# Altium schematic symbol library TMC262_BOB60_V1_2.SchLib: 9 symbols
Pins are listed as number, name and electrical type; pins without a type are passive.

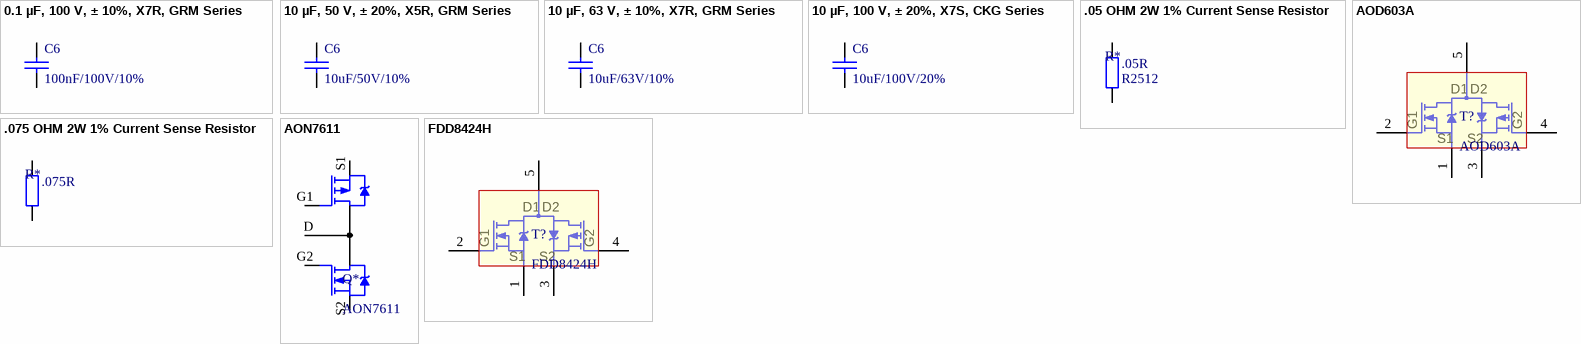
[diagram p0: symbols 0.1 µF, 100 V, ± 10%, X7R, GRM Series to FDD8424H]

## 0.1 µF, 100 V, ± 10%, X7R, GRM Series
designator C6, comment 100nF/100V/10%
SMD Multilayer Ceramic Capacitor, 0603 [1608 Metric], 0.1 µF, 100 V, ± 10%, X7R, GRM Series; MPN: GRM188R72A104KA35D; Type: MLCC; VoltageRating: 100V; ComponentLinknDescription: Datasheet; MF: MURATA; Capacitance: 100nF
footprint C0402 (0402 ceramic capacitor)
footprint C0603 (0603 ceramic capacitor)
footprint C0805 (0805 ceramic capacitor)
footprint C1206 (1206 ceramic capacitor)
footprint C1210 (1210 capacitor)
footprint C1812 (1812 capacitor)
pins: 1, 2

## 10 µF, 50 V, ± 20%, X5R, GRM Series
designator C6, comment 10uF/50V/10%
SMD Multilayer Ceramic Capacitor, 1206 [3216 Metric], 10 µF, 50 V, ± 20%, X5R, GRM Series; MPN: GRM31CR61H106MA12L; Type: MLCC; VoltageRating: 50V; ComponentLinknDescription: Datasheet; MF: MURATA; Capacitance: 10uF; Precision: 10%
footprint C0402 (0402 ceramic capacitor)
footprint C0603 (0603 ceramic capacitor)
footprint C0805 (0805 ceramic capacitor)
footprint C1206 (1206 ceramic capacitor)
footprint C1210 (1210 capacitor)
footprint C1812 (1812 capacitor)
pins: 1, 2

## 10 µF, 63 V, ± 10%, X7R, GRM Series
designator C6, comment 10uF/63V/10%
SMD Multilayer Ceramic Capacitor, 1210 [3225 Metric], 10 µF, 63 V, ± 10%, X7R, GRM Series; MPN: GRM32ER71J106KA12L; Type: MLCC; VoltageRating: 63V; ComponentLinknDescription: Datasheet; MF: MURATA; Capacitance: 10uF
footprint C0402 (0402 ceramic capacitor)
footprint C0603 (0603 ceramic capacitor)
footprint C0805 (0805 ceramic capacitor)
footprint C1206 (1206 ceramic capacitor)
footprint C1210 (1210 capacitor)
footprint C1812 (1812 capacitor)
pins: 1, 2

## 10 µF, 100 V, ± 20%, X7S, CKG Series
designator C6, comment 10uF/100V/20%
SMD Multilayer Ceramic Capacitor, 1812 [4532 Metric], 10 µF, 100 V, ± 20%, X7S, CKG Series; MPN: CKG45NX7S2A106M500JH; Type: MLCC; VoltageRating: 100V; ComponentLinknDescription: Datasheet; MF: TDK; Capacitance: 10uF
footprint C0402 (0402 ceramic capacitor)
footprint C0603 (0603 ceramic capacitor)
footprint C0805 (0805 ceramic capacitor)
footprint C1206 (1206 ceramic capacitor)
footprint C1210 (1210 capacitor)
footprint CKG45NX7S2A106M500JH (1812 STACKED capacitor)
pins: 1, 2

## .05 OHM 2W 1% Current Sense Resistor
designator R*, comment Resistance: .05R  (hidden comment: .05R / 2W / 1%)
Current Sense Resistor; MPN: LRC-LR2512LF-01-R050-F; VoltageRating: *V; Temp coefficient: *ppm; ComponentLinknDescription: Datasheet; MF: IRC / TT Electronics
footprint R0402 (0402 resistor)
footprint R0603 (0603 resistor)
footprint R0805 (0805 resistor)
footprint R1206 (1206 resistor)
footprint R2512 (2512 resistor)
footprint R0201 (0201 resistor)
footprint R1210 (1210 resistor)
footprint R1812 (1812 resistor)
footprint R2010 (2010 resistor)
footprint R2512 (2512 resistor)
pins: 1, 2

## .075 OHM 2W 1% Current Sense Resistor
designator R*, comment Resistance: .075R  (hidden comment: .075R / 2W / 1%)
SMD Current Sense Resistor, 0.075 ohm, 2 W, 2512 [6432 Metric], ± 1%, TLR Series; MPN: TLR3A20WR075FTDG; ComponentLinknDescription: Datasheet; MF: TE CONNECTIVITY
footprint R2512 (2512 resistor)
footprint R2512 (2512 resistor)
pins: 1, 2

## AOD603A
designator T?
Transistor: N/P-MOSFET; unipolar; complementary; -60/60V; TO252-4; MF: ALPHA & OMEGA SEMICONDUCTOR
footprint SOT114P991X239-6N (SOT223, 6-Leads, Body 6,54x9,91mm (avg), Pitch 1,14mm, IPC Medium Density)
pins: 1 S1, 2 G1, 3 S2, 4 G2, 5 D1/D2

## AON7611
designator Q*
Mosfet Array N and P-Channel, Common Drain 30V 9A, 18.5A 1.5W Surface Mount 8-DFN (3x3); SPL1_PN: 785-1404-1-ND; MF: Alpha & Omega Semiconductor Inc.
footprint AON7611
pins: D, G1, G2, S1, S2

## FDD8424H
designator T?
Dual MOSFET, N and P Channel, 9 A, 40 V, 0.019 ohm, 10 V, 1.7 V; MF: FAIRCHILD SEMICONDUCTOR
footprint SOT114P991X239-6N (SOT223, 6-Leads, Body 6,54x9,91mm (avg), Pitch 1,14mm, IPC Medium Density)
pins: 1 S1, 2 G1, 3 S2, 4 G2, 5 D1/D2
